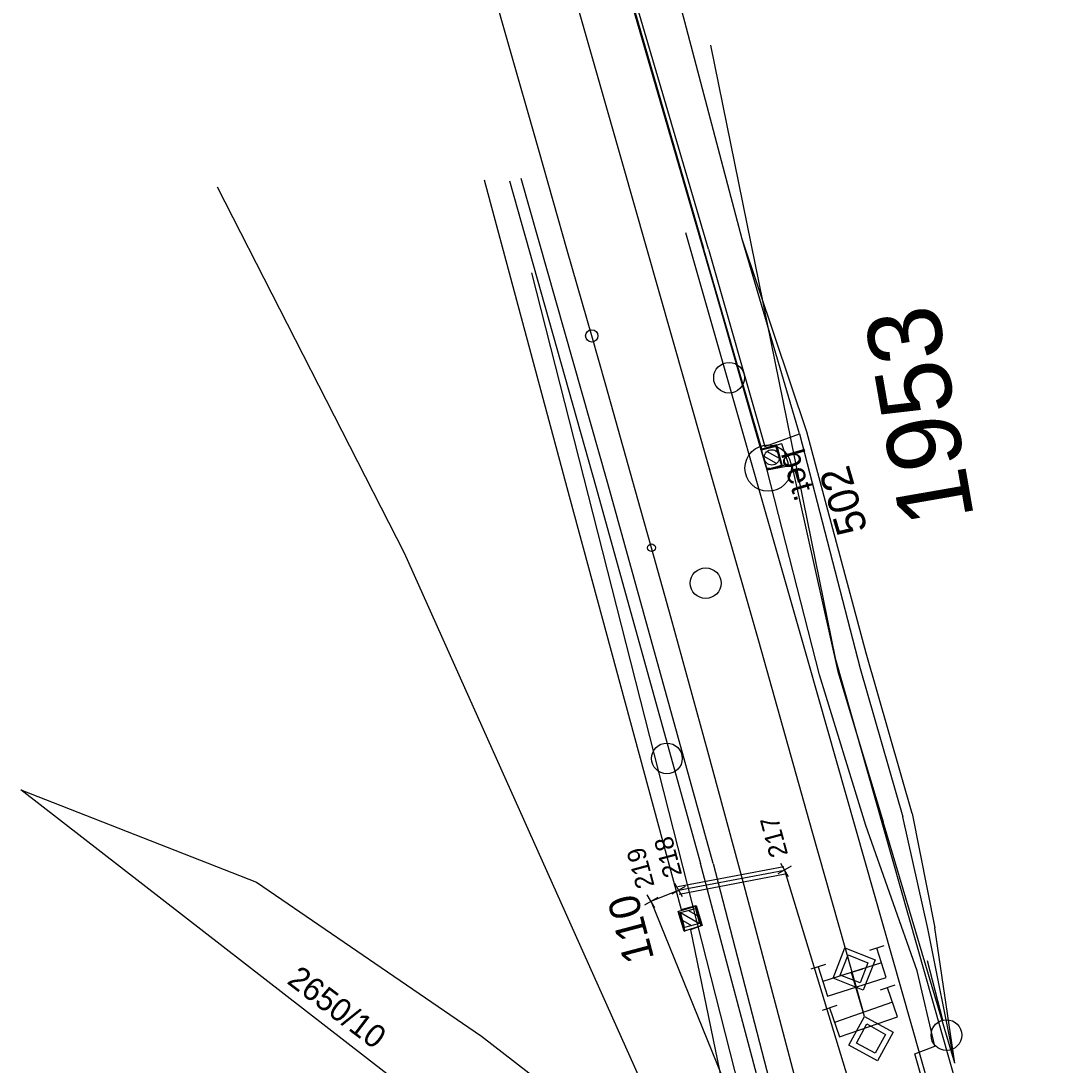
# Model space of a CAD drawing. Extents: x -754679 to -754173, y -1169241 to -1168288.
# Drawn here: x -754569.2 to -754502, y -1168428.5 to -1168360.5 of the extents above; entities that cross this region are included whole.
import ezdxf

# ---------------------------------------------------------------- set-up
doc = ezdxf.new("R2010")
doc.units = 0
for name, color, linetype in [('Vrstva 1', 7, 'Continuous'), ('Vrstva 11', 7, 'Continuous'), ('Vrstva 12', 7, 'Continuous'), ('Vrstva 13', 7, 'Continuous'), ('Vrstva 15', 7, 'Continuous'), ('Vrstva 16', 7, 'Continuous'), ('Vrstva 2', 7, 'Continuous'), ('Vrstva 36', 7, 'Continuous'), ('Vrstva 37', 7, 'Continuous'), ('Vrstva 4', 7, 'Continuous'), ('Vrstva 43', 7, 'Continuous'), ('Vrstva 45', 7, 'Continuous'), ('Vrstva 49', 7, 'Continuous'), ('Vrstva 53', 7, 'Continuous'), ('Vrstva 55', 7, 'Continuous'), ('Vrstva 57', 7, 'Continuous'), ('Vrstva 6', 7, 'Continuous'), ('Vrstva 60', 7, 'Continuous'), ('Vrstva 63', 7, 'Continuous')]:
    doc.layers.add(name, color=color, linetype=linetype)

msp = doc.modelspace()

# ---------------------------------------------------------------- linework, layer by layer
at = {"layer": 'Vrstva 1'}
for p, q in [((-754520.586, -1168389.665), (-754520.586, -1168389.665)), ((-754514.375, -1168425.111), (-754515.119, -1168422.492))]:
    msp.add_line(p, q, dxfattribs=at)
for points in [[(-754515.119, -1168422.492), (-754517.719, -1168413.318), (-754521.199, -1168400.933), (-754522.017, -1168398.049), (-754524.114, -1168390.706), (-754525.989, -1168384.139), (-754528.539, -1168375.211), (-754530.055, -1168369.875), (-754532.617, -1168360.912), (-754535.19, -1168351.885)], [(-754532.075, -1168381.055), (-754533.644, -1168375.559), (-754535.526, -1168368.953), (-754537.579, -1168361.758), (-754540.042, -1168353.12)], [(-754513.352, -1168450.618), (-754515.29, -1168443.036), (-754517.542, -1168434.317), (-754517.919, -1168432.843), (-754519.829, -1168425.595), (-754522.159, -1168416.85), (-754524.525, -1168408.114), (-754526.908, -1168399.431), (-754528.183, -1168394.853), (-754528.892, -1168392.323), (-754531.158, -1168384.271), (-754532.075, -1168381.055)]]:
    msp.add_lwpolyline(points, dxfattribs=at)
for centre, radius in [((-754532.075, -1168381.055), 0.4), ((-754528.183, -1168394.853), 0.25)]:
    msp.add_circle(centre, radius, dxfattribs=at)
at = {"layer": 'Vrstva 11'}
for p, q in [((-754519.852, -1168389.032), (-754520.665, -1168388.59)), ((-754520.037, -1168389.358), (-754520.839, -1168388.921)), ((-754526.284, -1168418.612), (-754525.066, -1168419.321)), ((-754525.772, -1168418.476), (-754525.201, -1168418.808)), ((-754526.152, -1168419.122), (-754525.574, -1168419.458))]:
    msp.add_line(p, q, dxfattribs=at)
msp.add_lwpolyline([(-754525.321, -1168418.357), (-754525.065, -1168419.323), (-754526.031, -1168419.579), (-754526.287, -1168418.613)], close=True, dxfattribs=at)
msp.add_lwpolyline([(-754525.321, -1168418.357), (-754525.065, -1168419.323), (-754526.031, -1168419.579), (-754526.287, -1168418.613), (-754525.321, -1168418.357)], dxfattribs=at)
msp.add_circle((-754520.344, -1168388.968), 0.5, dxfattribs=at)
at = {"layer": 'Vrstva 12'}
for p, q in [((-754521.038, -1168388.456), (-754520.025, -1168388.209)), ((-754521.038, -1168388.456), (-754521.024, -1168388.472)), ((-754520.659, -1168389.778), (-754521.038, -1168388.456)), ((-754521.024, -1168388.472), (-754520.061, -1168388.233)), ((-754520.647, -1168389.754), (-754521.024, -1168388.472)), ((-754520.025, -1168388.209), (-754520.061, -1168388.233)), ((-754520.061, -1168388.233), (-754519.713, -1168389.5)), ((-754520.025, -1168388.209), (-754519.675, -1168389.537)), ((-754519.675, -1168389.537), (-754520.659, -1168389.778)), ((-754519.713, -1168389.5), (-754520.647, -1168389.754)), ((-754519.675, -1168389.537), (-754519.713, -1168389.5)), ((-754520.659, -1168389.778), (-754520.647, -1168389.754)), ((-754526.438, -1168418.549), (-754525.302, -1168418.183)), ((-754526.438, -1168418.549), (-754526.417, -1168418.543)), ((-754526.048, -1168419.824), (-754526.438, -1168418.549)), ((-754525.316, -1168418.213), (-754526.417, -1168418.543)), ((-754526.417, -1168418.543), (-754526.02, -1168419.794)), ((-754525.316, -1168418.213), (-754525.302, -1168418.183)), ((-754524.956, -1168419.445), (-754525.316, -1168418.213)), ((-754525.302, -1168418.183), (-754524.947, -1168419.473)), ((-754526.02, -1168419.794), (-754524.956, -1168419.445)), ((-754524.947, -1168419.473), (-754524.956, -1168419.445)), ((-754524.947, -1168419.473), (-754526.048, -1168419.824)), ((-754526.048, -1168419.824), (-754526.02, -1168419.794))]:
    msp.add_line(p, q, dxfattribs=at)
at = {"layer": 'Vrstva 13'}
for p, q in [((-754532.986, -1168347.056), (-754524.793, -1168375.353)), ((-754521.002, -1168388.434), (-754524.793, -1168375.353)), ((-754521.059, -1168388.474), (-754520.042, -1168388.157)), ((-754520.042, -1168388.157), (-754521.002, -1168388.434)), ((-754521.002, -1168388.434), (-754521.059, -1168388.474))]:
    msp.add_line(p, q, dxfattribs=at)
at = {"layer": 'Vrstva 15'}
for p, q in [((-754513.046, -1168420.773), (-754513.998, -1168421.08)), ((-754516.853, -1168422), (-754517.805, -1168422.307)), ((-754513.215, -1168421.878), (-754517.023, -1168423.106)), ((-754512.341, -1168423.347), (-754513.285, -1168423.675)), ((-754516.12, -1168424.658), (-754517.065, -1168424.985)), ((-754512.485, -1168424.456), (-754516.265, -1168425.766))]:
    msp.add_line(p, q, dxfattribs=at)
for points in [[(-754517.329, -1168422.154), (-754516.716, -1168424.057), (-754512.909, -1168422.83), (-754513.522, -1168420.927)], [(-754516.592, -1168424.821), (-754515.937, -1168426.711), (-754512.158, -1168425.401), (-754512.813, -1168423.511)]]:
    msp.add_lwpolyline(points, dxfattribs=at)
at = {"layer": 'Vrstva 16'}
for p, q in [((-754524.474, -1168375.405), (-754532.831, -1168346.995)), ((-754518.545, -1168387.436), (-754522.285, -1168374.75)), ((-754518.079, -1168387.295), (-754522.285, -1168374.75)), ((-754524.474, -1168375.405), (-754520.806, -1168388.26)), ((-754518.545, -1168387.436), (-754514.606, -1168402.714)), ((-754514.197, -1168401.728), (-754518.079, -1168387.295)), ((-754519.045, -1168389.486), (-754520.659, -1168389.799)), ((-754519.045, -1168389.486), (-754516.042, -1168402.912)), ((-754511.201, -1168412.167), (-754514.197, -1168401.728)), ((-754516.042, -1168402.912), (-754513.097, -1168412.704)), ((-754514.606, -1168402.714), (-754511.81, -1168412.37)), ((-754510.181, -1168419.647), (-754511.81, -1168412.37)), ((-754511.201, -1168412.167), (-754509.728, -1168419.605)), ((-754508.44, -1168428.416), (-754513.097, -1168412.704)), ((-754508.44, -1168428.416), (-754510.181, -1168419.647)), ((-754508.44, -1168428.416), (-754509.728, -1168419.605))]:
    msp.add_line(p, q, dxfattribs=at)
for points in [[(-754522.285, -1168374.75), (-754529.837, -1168346.107), (-754530.726, -1168345.353)], [(-754520.806, -1168388.26), (-754518.545, -1168387.436)], [(-754520.108, -1168388.203), (-754519.72, -1168389.511), (-754519.272, -1168389.393), (-754519.697, -1168388.084), (-754520.108, -1168388.203)]]:
    msp.add_lwpolyline(points, dxfattribs=at)
at = {"layer": 'Vrstva 36'}
for points in [[(-754526.467, -1168416.914), (-754519.567, -1168415.604)], [(-754526.373, -1168417.406), (-754519.473, -1168416.096)]]:
    msp.add_lwpolyline(points, dxfattribs=at)
at = {"layer": 'Vrstva 37'}
for p, q in [((-754509.225, -1168425.625), (-754510.214, -1168421.749)), ((-754508.978, -1168426.594), (-754508.978, -1168426.594))]:
    msp.add_line(p, q, dxfattribs=at)
msp.add_circle((-754508.978, -1168426.594), 1, dxfattribs=at)
at = {"layer": 'Vrstva 4'}
for p, q in [((-754531.397, -1168352.752), (-754524.112, -1168377.878)), ((-754539.069, -1168370.891), (-754533.54, -1168391.487)), ((-754537.425, -1168370.968), (-754531.781, -1168390.961)), ((-754531.029, -1168390.667), (-754536.669, -1168370.803)), ((-754520.659, -1168389.799), (-754521.044, -1168388.476)), ((-754524.175, -1168415.408), (-754531.029, -1168390.667)), ((-754533.54, -1168391.487), (-754526.26, -1168418.409)), ((-754531.781, -1168390.961), (-754524.994, -1168415.424)), ((-754510.895, -1168422.409), (-754514.218, -1168412.95)), ((-754519.8, -1168434.851), (-754524.994, -1168415.424)), ((-754524.175, -1168415.408), (-754519.17, -1168434.706))]:
    msp.add_line(p, q, dxfattribs=at)
for points in [[(-754524.112, -1168377.878), (-754521.059, -1168388.474), (-754521.044, -1168388.476)], [(-754514.218, -1168412.95), (-754517.253, -1168403.134), (-754520.659, -1168389.799)], [(-754526.26, -1168418.409), (-754525.277, -1168418.156), (-754524.888, -1168419.45), (-754525.652, -1168419.742), (-754522.423, -1168435.314)], [(-754509.785, -1168444.748), (-754512.458, -1168433.522), (-754510.833, -1168432.986), (-754510.108, -1168431.068), (-754511.036, -1168427.816), (-754509.739, -1168427.312), (-754510.895, -1168422.409)]]:
    msp.add_lwpolyline(points, dxfattribs=at)
at = {"layer": 'Vrstva 43'}
for centre in [(-754523.135, -1168383.782), (-754524.655, -1168397.16), (-754527.181, -1168408.574)]:
    msp.add_circle(centre, 1, dxfattribs=at)
at = {"layer": 'Vrstva 45'}
msp.add_lwpolyline([(-754519.47, -1168446.863), (-754518.79, -1168445.56), (-754518.97, -1168444.66), (-754520.27, -1168437.46), (-754528.21, -1168417.88), (-754526.42, -1168417.16), (-754519.52, -1168415.85), (-754514.96, -1168430.83), (-754510.674, -1168447.87), (-754509.4, -1168450.23)], dxfattribs=at)
at = {"layer": 'Vrstva 49'}
msp.add_line((-754524.947, -1168419.473), (-754525.302, -1168418.183), dxfattribs=at)
at = {"layer": 'Vrstva 53'}
for p, q in [((-754524.35, -1168362.13), (-754516.22, -1168402.04)), ((-754544.26, -1168395.2), (-754556.45, -1168371.36)), ((-754525.37, -1168437.38), (-754544.26, -1168395.2)), ((-754516.22, -1168402.04), (-754501.97, -1168452.25)), ((-754520.37, -1168448.54), (-754569.24, -1168410.61)), ((-754569.24, -1168410.61), (-754553.89, -1168416.63)), ((-754553.89, -1168416.63), (-754539.25, -1168426.67)), ((-754539.25, -1168426.67), (-754525.37, -1168437.38))]:
    msp.add_line(p, q, dxfattribs=at)
at = {"layer": 'Vrstva 55'}
for p, q in [((-754525.96, -1168374.32), (-754517.96, -1168402.36)), ((-754517.36, -1168450.11), (-754535.97, -1168376.96)), ((-754517.96, -1168402.36), (-754506.68, -1168442.02))]:
    msp.add_line(p, q, dxfattribs=at)
at = {"layer": 'Vrstva 6'}
for p, q in [((-754519.087, -1168415.6), (-754519.953, -1168416.1)), ((-754519.27, -1168416.283), (-754519.77, -1168415.417)), ((-754526.17, -1168417.593), (-754526.67, -1168416.727)), ((-754525.987, -1168416.91), (-754526.853, -1168417.41)), ((-754527.777, -1168417.63), (-754528.643, -1168418.13)), ((-754527.96, -1168418.313), (-754528.46, -1168417.447)), ((-754514.439, -1168422.299), (-754515.877, -1168422.723)), ((-754514.311, -1168425.389), (-754515.158, -1168422.511))]:
    msp.add_line(p, q, dxfattribs=at)
for points in [[(-754515.589, -1168420.917), (-754513.623, -1168421.684), (-754514.392, -1168423.655), (-754516.36, -1168422.893), (-754515.589, -1168420.917)], [(-754514.092, -1168421.889), (-754514.594, -1168423.193), (-754515.902, -1168422.692), (-754515.388, -1168421.375), (-754514.092, -1168421.889)], [(-754514.311, -1168425.389), (-754512.459, -1168426.401), (-754513.472, -1168428.259), (-754515.326, -1168427.251), (-754514.311, -1168425.389)], [(-754514.169, -1168425.868), (-754512.947, -1168426.545), (-754513.615, -1168427.772), (-754514.846, -1168427.11), (-754514.169, -1168425.868)]]:
    msp.add_lwpolyline(points, dxfattribs=at)
at = {"layer": 'Vrstva 63'}
msp.add_line((-754520.686, -1168389.665), (-754520.486, -1168389.665), dxfattribs=at)
msp.add_circle((-754520.586, -1168389.665), 1.512, dxfattribs=at)

# ---------------------------------------------------------------- texts
at = {"layer": 'Vrstva 11'}
for s, rotation, p in [('502', 106.45023, (-754514.096, -1168393.66)), ('110', 104.81895, (-754527.997, -1168421.595))]:
    msp.add_text(s, height=2, rotation=rotation, dxfattribs=at).set_placement(p)
at = {"layer": 'Vrstva 16'}
msp.add_text('bet.', height=1.5, rotation=286.52226, dxfattribs=at).set_placement((-754519.769, -1168388.724))
at = {"layer": 'Vrstva 2'}
msp.add_text('1953', height=4.8, rotation=99.89041, dxfattribs=at).set_placement((-754507.169, -1168392.909))
at = {"layer": 'Vrstva 57'}
msp.add_text('2650/10', height=1.5, rotation=322.74713, dxfattribs=at).set_placement((-754551.984, -1168423.176))
at = {"layer": 'Vrstva 60'}
for s, p in [('217', (-754519.284, -1168414.831)), ('218', (-754526.184, -1168416.141)), ('219', (-754527.974, -1168416.861))]:
    msp.add_text(s, height=1.2, rotation=105, dxfattribs=at).set_placement(p)

doc.saveas('drawing.dxf')
